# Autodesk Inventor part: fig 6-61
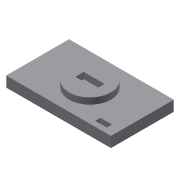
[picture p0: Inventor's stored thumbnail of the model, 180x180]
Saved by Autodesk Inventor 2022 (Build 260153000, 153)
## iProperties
Created: 2007-01
Part Number: fig 6-61
Document SubType Name: Modeling
Designer: Administrator
Density: 1 g/cm^3
Material: Generic
Appearance: Default
Author: Administrator
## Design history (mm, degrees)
sketch "Sketch1"
  geometry: L1 (-50, 30)-(50, 30); L2 (50, 30)-(50, -30); L3 (50, -30)-(-50, -30); L4 (-50, -30)-(-50, 30); 1 further point
  constraints: 8 end point, 2 parallel, 1 horizontal, 1 perpendicular, 1 other
  dimensions: "d0" = 50 distance from line of L4 point (0, 0); "d1" = 100 distance of L1.start L1.end; "d2" = 30 distance from line of L3 point (0, 0); "d3" = 60 distance between parallel lines of L3 L1
extrude "Extrusion1" new body sketch "Sketch1" distance "d4" = 10; taper "d5" = 0 deg
sketch "Sketch2"
  geometry: L1 (10, -4)-(-10, -4); L2 (-10, -4)-(-10, 4); L3 (-10, 4)-(10, 4); L4 (10, 4)-(10, -4); C1 r 20 at (0, 0); 1 further point
  constraints: 8 end point, 2 parallel, 1 centre point, 1 coincident, 1 horizontal, 1 perpendicular, 1 other
  dimensions: "d6" = 40 diameter of C1; "d7" = 4 distance from line of L3 point (0, 0); "d8" = 8 distance between parallel lines of L1 L3; "d9" = 10 distance from line of L2 point (0, 0); "d10" = 20 distance between parallel lines of L4 L2
extrude "Extrusion2" join sketch "Sketch2" distance "d11" = 6; taper "d12" = 0 deg
sketch "Sketch3"
  geometry: L1 (30, -20)-(41, -20); L2 (41, -20)-(41, -25); L3 (41, -25)-(30, -25); L4 (30, -25)-(30, -20)
  constraints: 8 end point, 2 parallel, 1 horizontal, 1 perpendicular
extrude "Extrusion3" cut sketch "Sketch3" extent not by distance; stored distance "d13" = 10; taper "d14" = 0 deg
body "Solid1"
